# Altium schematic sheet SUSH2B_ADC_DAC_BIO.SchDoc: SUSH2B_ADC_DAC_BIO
size C; Organization: LIGO Laboratory; Address1: California Institute of Technology; Address2: Massachusetts Institute of Technology; DocumentNumber: D0902810; Revision: v10; SheetNumber: 11; SheetTotal: 14; Engineer: J.Kissel/L.Sánchez
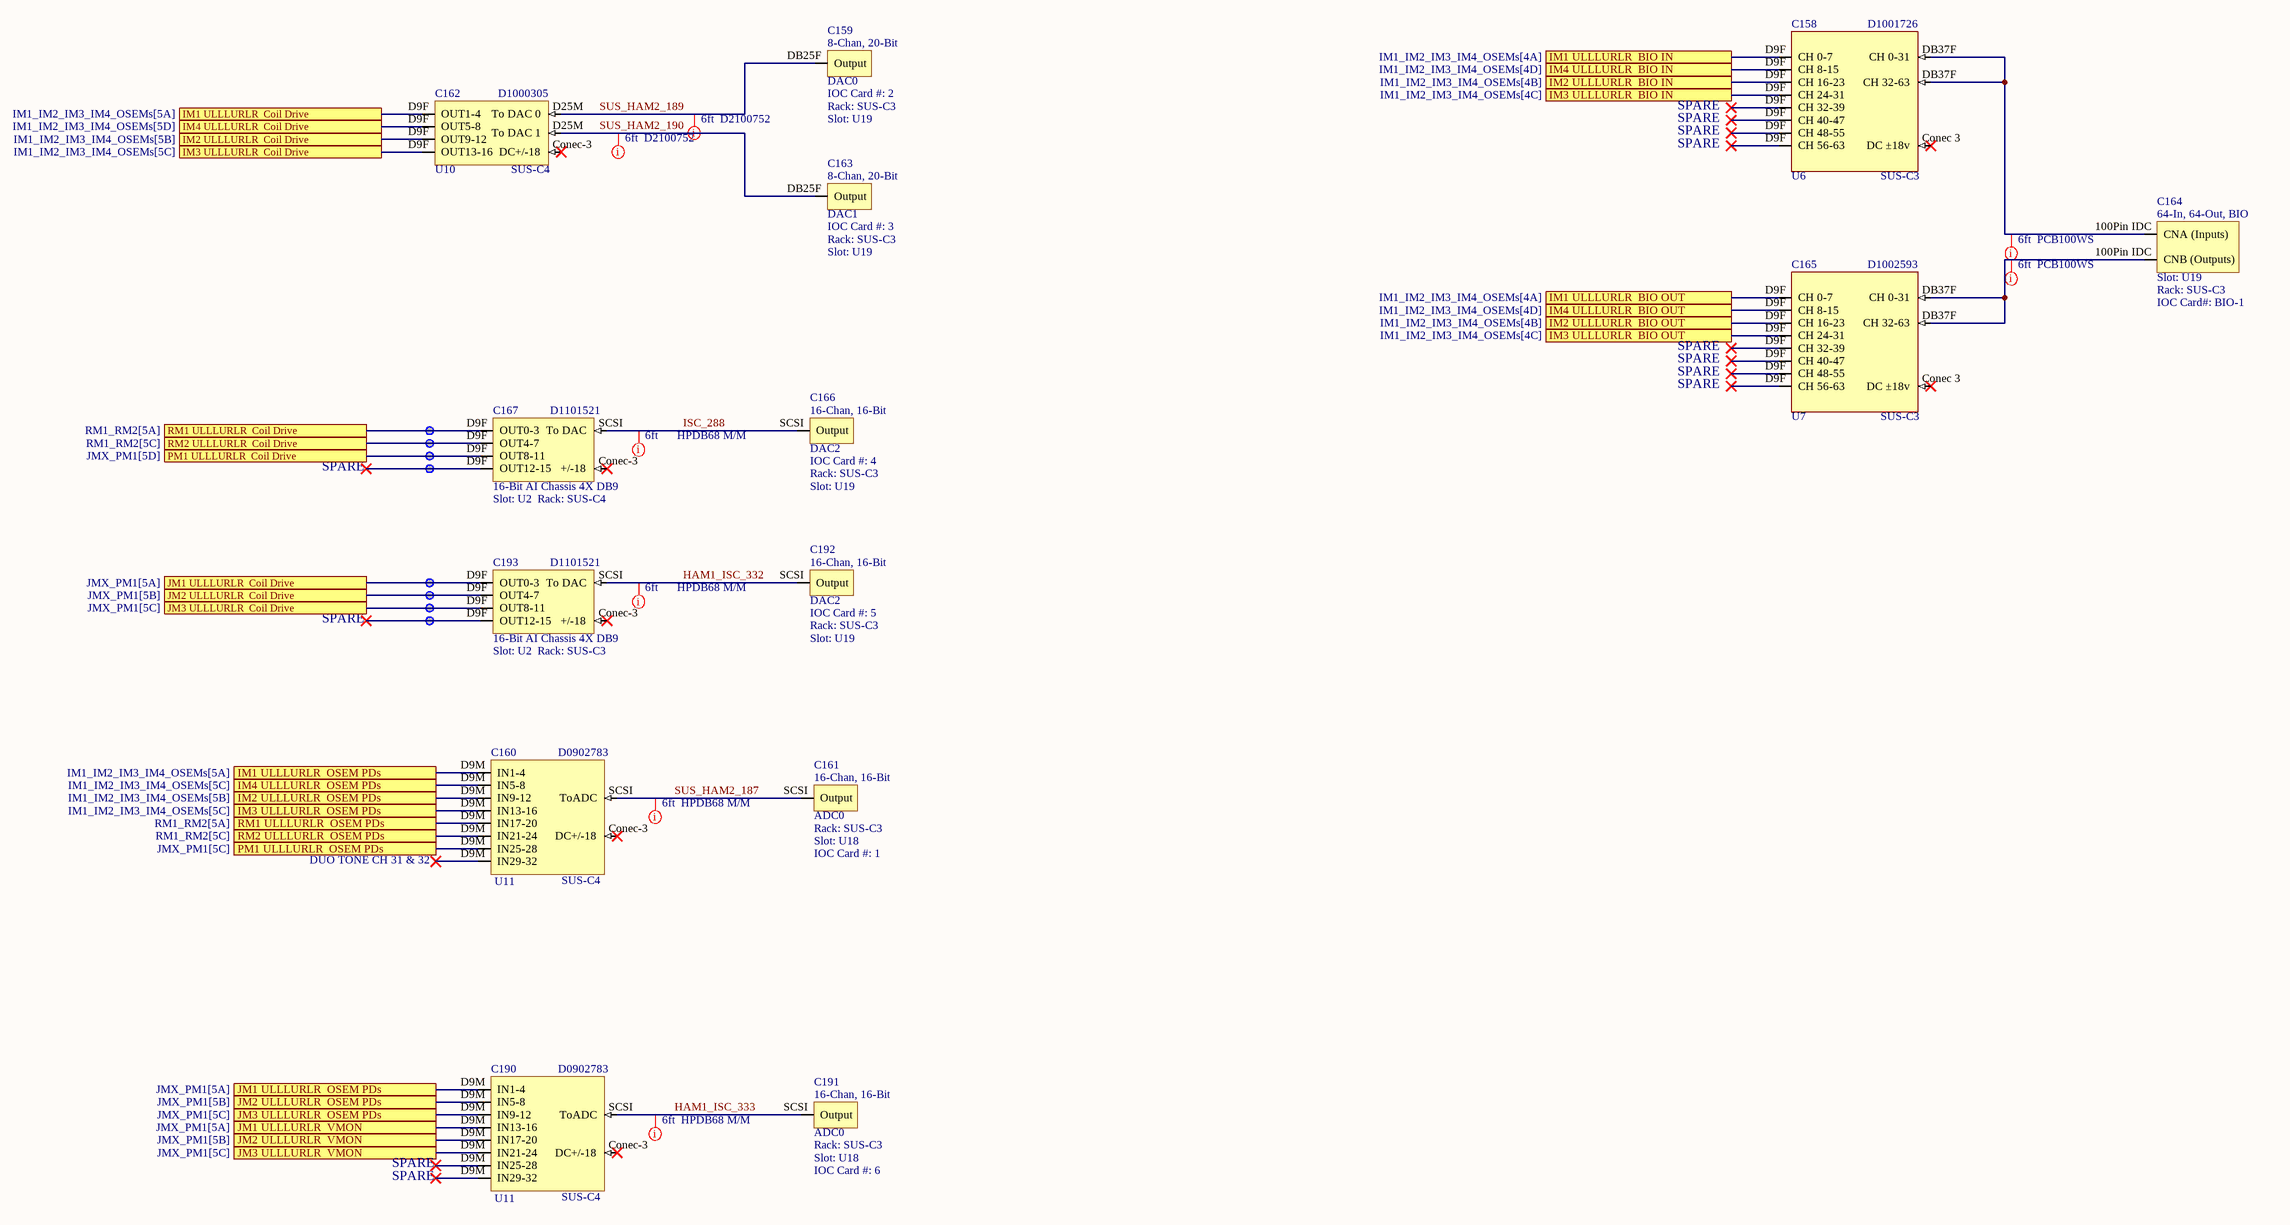
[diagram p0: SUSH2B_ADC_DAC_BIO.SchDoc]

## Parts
C158  Slot: U6  Rack: SUS-C3  DCC: D1001726  (hidden comment: BI D1001726 Monitors_8xDB9)
C159  DAC0  IOC Card #: 2  Rack: SUS-C3  Slot: U19
C160  DCC: D0902783  Rack: SUS-C4  Slot: U11  (hidden comment: AA D0902783 8xD9)
C161  ADC0  Rack: SUS-C3  Slot: U18  IOC Card #: 1
C162  Rack: SUS-C4  Slot: U10  DCC: D1000305  (hidden comment: AI D1000305 4xD9 18_20_Bit)
C163  DAC1  IOC Card #: 3  Rack: SUS-C3  Slot: U19
C164  Slot: U19  Rack: SUS-C3  IOC Card#: BIO-1  (hidden comment: BIO Contec Card 64Ix64O)
C165  Slot: U7  Rack: SUS-C3  DCC: D1002593  (hidden comment: BO D1002593 Commands_8xDB9)
C166  DAC2  IOC Card #: 4  Rack: SUS-C3  Slot: U19
C167  16-Bit AI Chassis 4X DB9  DCC: D1101521  Rack: SUS-C4  Slot: U2
C190  DCC: D0902783  Rack: SUS-C4  Slot: U11  (hidden comment: AA D0902783 8xD9)
C191  ADC0  Rack: SUS-C3  Slot: U18  IOC Card #: 6
C192  DAC2  IOC Card #: 5  Rack: SUS-C3  Slot: U19
C193  16-Bit AI Chassis 4X DB9  DCC: D1101521  Rack: SUS-C3  Slot: U2

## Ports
IM1 ULLLURLR  BIO IN (see IM1_IM2_IM3_IM4_OSEMs[4A]), IM1 ULLLURLR  BIO OUT (see IM1_IM2_IM3_IM4_OSEMs[4A]), IM1 ULLLURLR  Coil Drive (see IM1_IM2_IM3_IM4_OSEMs[5A]), IM1 ULLLURLR  OSEM PDs (see IM1_IM2_IM3_IM4_OSEMs[5A]), IM2 ULLLURLR  BIO IN (see IM1_IM2_IM3_IM4_OSEMs[4B]), IM2 ULLLURLR  BIO OUT (see IM1_IM2_IM3_IM4_OSEMs[4B]), IM2 ULLLURLR  Coil Drive (see IM1_IM2_IM3_IM4_OSEMs[5B]), IM2 ULLLURLR  OSEM PDs (see IM1_IM2_IM3_IM4_OSEMs[5B]), IM3 ULLLURLR  BIO IN (see IM1_IM2_IM3_IM4_OSEMs[4C]), IM3 ULLLURLR  BIO OUT (see IM1_IM2_IM3_IM4_OSEMs[4C]), IM3 ULLLURLR  Coil Drive (see IM1_IM2_IM3_IM4_OSEMs[5C]), IM3 ULLLURLR  OSEM PDs (see IM1_IM2_IM3_IM4_OSEMs[5C]), IM4 ULLLURLR  BIO IN (see IM1_IM2_IM3_IM4_OSEMs[4D]), IM4 ULLLURLR  BIO OUT (see IM1_IM2_IM3_IM4_OSEMs[4D]), IM4 ULLLURLR  Coil Drive (see IM1_IM2_IM3_IM4_OSEMs[5D]), IM4 ULLLURLR  OSEM PDs (see IM1_IM2_IM3_IM4_OSEMs[5C]), JM1 ULLLURLR  Coil Drive (see JMX_PM1[5A]), JM1 ULLLURLR  OSEM PDs (see JMX_PM1[5A]), JM1 ULLLURLR  VMON (see JMX_PM1[5A]), JM2 ULLLURLR  Coil Drive (see JMX_PM1[5B]), JM2 ULLLURLR  OSEM PDs (see JMX_PM1[5B]), JM2 ULLLURLR  VMON (see JMX_PM1[5B]), JM3 ULLLURLR  Coil Drive (see JMX_PM1[5C]), JM3 ULLLURLR  OSEM PDs (see JMX_PM1[5C]), JM3 ULLLURLR  VMON (see JMX_PM1[5C]), PM1 ULLLURLR  Coil Drive (see JMX_PM1[5D]), PM1 ULLLURLR  OSEM PDs (see JMX_PM1[5C]), RM1 ULLLURLR  Coil Drive (see RM1_RM2[5A]), RM1 ULLLURLR  OSEM PDs (see RM1_RM2[5A]), RM2 ULLLURLR  Coil Drive (see RM1_RM2[5C]), RM2 ULLLURLR  OSEM PDs (see RM1_RM2[5C])

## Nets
HAM1_ISC_332: C192.SCSI(Output) C193.SCSI(To_DAC)
HAM1_ISC_333: C190.SCSI(ToADC) C191.SCSI(Output)
IM1 ULLLURLR  BIO IN: C158.D9F(CH_0-7) ; port IM1 ULLLURLR  BIO IN
IM1 ULLLURLR  BIO OUT: C165.D9F(CH_0-7) ; port IM1 ULLLURLR  BIO OUT
IM1 ULLLURLR  Coil Drive: C162.D9F(OUT1-4) ; port IM1 ULLLURLR  Coil Drive
IM1 ULLLURLR  OSEM PDs: C160.D9M(IN1-4) ; port IM1 ULLLURLR  OSEM PDs
IM2 ULLLURLR  BIO IN: C158.D9F(CH_16-23) ; port IM2 ULLLURLR  BIO IN
IM2 ULLLURLR  BIO OUT: C165.D9F(CH_16-23) ; port IM2 ULLLURLR  BIO OUT
IM2 ULLLURLR  Coil Drive: C162.D9F(OUT9-12) ; port IM2 ULLLURLR  Coil Drive
IM2 ULLLURLR  OSEM PDs: C160.D9M(IN9-12) ; port IM2 ULLLURLR  OSEM PDs
IM3 ULLLURLR  BIO IN: C158.D9F(CH_24-31) ; port IM3 ULLLURLR  BIO IN
IM3 ULLLURLR  BIO OUT: C165.D9F(CH_24-31) ; port IM3 ULLLURLR  BIO OUT
IM3 ULLLURLR  Coil Drive: C162.D9F(OUT13-16) ; port IM3 ULLLURLR  Coil Drive
IM3 ULLLURLR  OSEM PDs: C160.D9M(IN13-16) ; port IM3 ULLLURLR  OSEM PDs
IM4 ULLLURLR  BIO IN: C158.D9F(CH_8-15) ; port IM4 ULLLURLR  BIO IN
IM4 ULLLURLR  BIO OUT: C165.D9F(CH_8-15) ; port IM4 ULLLURLR  BIO OUT
IM4 ULLLURLR  Coil Drive: C162.D9F(OUT5-8) ; port IM4 ULLLURLR  Coil Drive
IM4 ULLLURLR  OSEM PDs: C160.D9M(IN5-8) ; port IM4 ULLLURLR  OSEM PDs
ISC_288: C166.SCSI(Output) C167.SCSI(To_DAC)
JM1 ULLLURLR  Coil Drive: C193.D9F(OUT0-3) ; port JM1 ULLLURLR  Coil Drive
JM1 ULLLURLR  OSEM PDs: C190.D9M(IN1-4) ; port JM1 ULLLURLR  OSEM PDs
JM1 ULLLURLR  VMON: C190.D9M(IN13-16) ; port JM1 ULLLURLR  VMON
JM2 ULLLURLR  Coil Drive: C193.D9F(OUT4-7) ; port JM2 ULLLURLR  Coil Drive
JM2 ULLLURLR  OSEM PDs: C190.D9M(IN5-8) ; port JM2 ULLLURLR  OSEM PDs
JM2 ULLLURLR  VMON: C190.D9M(IN17-20) ; port JM2 ULLLURLR  VMON
JM3 ULLLURLR  Coil Drive: C193.D9F(OUT8-11) ; port JM3 ULLLURLR  Coil Drive
JM3 ULLLURLR  OSEM PDs: C190.D9M(IN9-12) ; port JM3 ULLLURLR  OSEM PDs
JM3 ULLLURLR  VMON: C190.D9M(IN21-24) ; port JM3 ULLLURLR  VMON
PM1 ULLLURLR  Coil Drive: C167.D9F(OUT8-11) ; port PM1 ULLLURLR  Coil Drive
PM1 ULLLURLR  OSEM PDs: C160.D9M(IN25-28) ; port PM1 ULLLURLR  OSEM PDs
RM1 ULLLURLR  Coil Drive: C167.D9F(OUT0-3) ; port RM1 ULLLURLR  Coil Drive
RM1 ULLLURLR  OSEM PDs: C160.D9M(IN17-20) ; port RM1 ULLLURLR  OSEM PDs
RM2 ULLLURLR  Coil Drive: C167.D9F(OUT4-7) ; port RM2 ULLLURLR  Coil Drive
RM2 ULLLURLR  OSEM PDs: C160.D9M(IN21-24) ; port RM2 ULLLURLR  OSEM PDs
SUS_HAM2_187: C160.SCSI(ToADC) C161.SCSI(Output)
SUS_HAM2_189: C159.DB25F(Output) C162.D25M(To_DAC_0)
SUS_HAM2_190: C162.D25M(To_DAC_1) C163.DB25F(Output)
NetC158_DB37F: C158.DB37F(CH_0-31) C164.100Pin_IDC(CNA_(Inputs))
NetC164_100Pin IDC: C164.100Pin_IDC(CNB_(Outputs)) C165.DB37F(CH_0-31)

Not connected (* = marked no-connect by the designer): C158 Conec 3(DC_±18v)*; C160 Conec-3(DC+/-18)*; C162 Conec-3(DC+/-18)*; C165 Conec 3(DC_±18v)*; C167 Conec-3(+/-18)*; C190 Conec-3(DC+/-18)*; C193 Conec-3(+/-18)*

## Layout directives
Length: 6ft; DCC: HPDB68 M/M: HAM1_ISC_332, HAM1_ISC_333, ISC_288, SUS_HAM2_187
Length: 6ft; DCC: D2100752: SUS_HAM2_189, SUS_HAM2_190
Length: 6ft; DCC: PCB100WS: NetC158_DB37F, NetC164_100Pin IDC

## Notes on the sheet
- SPARE
- DUO TONE CH 31 & 32

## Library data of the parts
C158 = BI D1001726 Monitors_8xDB9: Serial: Sxxxxxxx; System: SUS
C159 C163 = DAC-20: 8 Chan, 20 Bit DAC
C160 C190 = AA D0902783 8xD9: Serial: Sxxxxxxx; System: SUS
C161 C191 = ADC-16: 16 Chan, 16 Bit ADC
C162 = AI D1000305 4xD9 18_20_Bit: System: SUS; Serial: Sxxxxxxx
C164 = BIO Contec Card 64Ix64O: System: SUS
C165 = BO D1002593 Commands_8xDB9: Serial: Sxxxxxxx; System: SUS
C166 C192 = DAC-16: 16 Chan, 16 Bit DAC
C167 C193 = AI_9pin_16_bit: AI Chassis 4X DB9 16-bit; Serial: Sxxxxxxx; System: ISC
